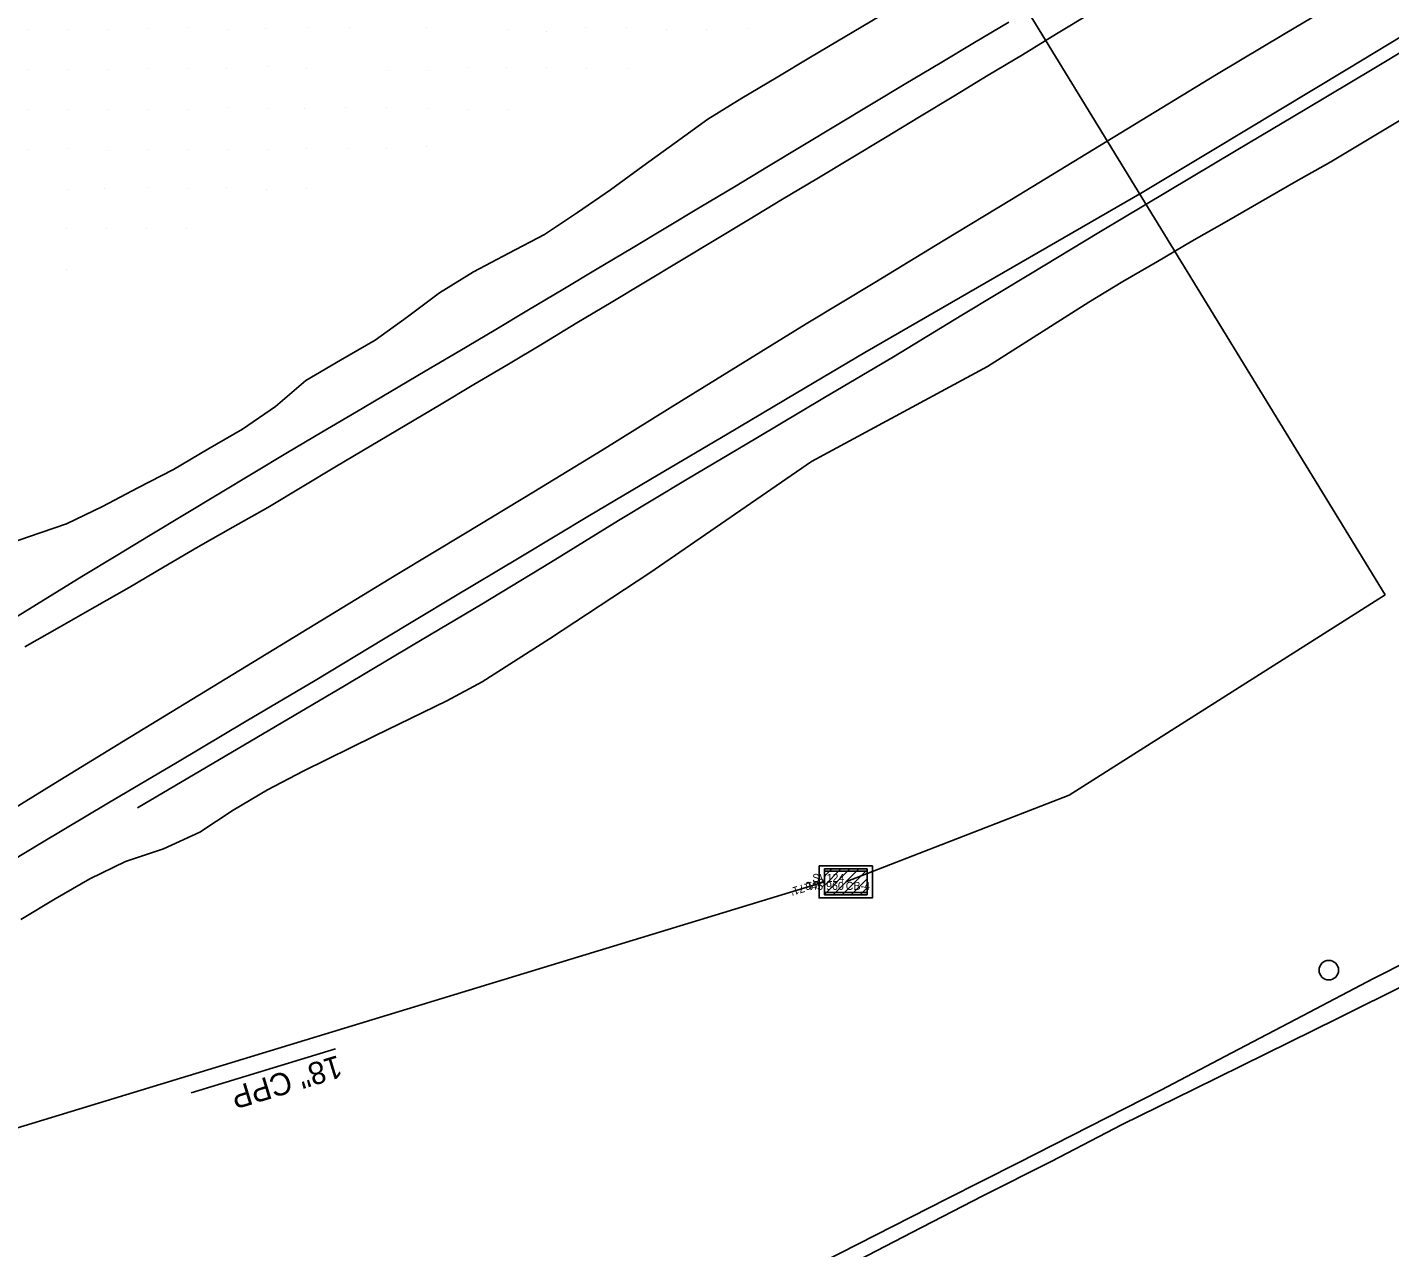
# Model space of a CAD drawing. Extents: x 2262025 to 2264532, y 740981 to 742724.
# Drawn here: x 2263228.5 to 2263398.7, y 741736.1 to 741888.7 of the extents above; entities that cross this region are included whole.
import ezdxf

# ---------------------------------------------------------------- set-up
doc = ezdxf.new("R2010")
doc.units = 0
for name, color, linetype in [('DR_X_Storm_Sewer', 7, 'Continuous'), ('DR_X_Text', 7, 'Continuous'), ('GE_X_Alignment_100_Bearings', 7, 'Continuous'), ('GE_X_Alignment_100_Cardinal_Points', 7, 'Continuous'), ('GE_X_Alignment_100_Curve_Data', 7, 'Continuous'), ('GE_X_Alignment_100_Stations', 7, 'Continuous'), ('Ground Shots', 7, 'Continuous'), ('HY_X_Spring_Cells', 7, 'Continuous'), ('RS_Raster1', 7, 'Continuous'), ('RW_X_CL', 7, 'Continuous'), ('RW_X_CL_1000_Distances', 7, 'Continuous'), ('RW_X_CL_100_Curve_Data', 7, 'Continuous'), ('RW_X_CL_100_Stations', 7, 'Continuous'), ('RW_X_CL_500_Curve_Data', 7, 'Continuous'), ('RW_X_CL_500_Stations', 7, 'Continuous'), ('SV_X_Control_Cells_Found', 7, 'Continuous'), ('SV_X_Text_Comment', 7, 'Continuous')]:
    doc.layers.add(name, color=color, linetype=linetype)

msp = doc.modelspace()

# ---------------------------------------------------------------- linework, layer by layer
at = {"layer": 'DR_X_Storm_Sewer'}
msp.add_line((2263328.09, 741781.86), (2263190.44, 741739.91), dxfattribs=at)
at = {"layer": 'DR_X_Text'}
msp.add_line((2263248.95, 741755.5), (2263267, 741761), dxfattribs=at)
at = {"layer": 'GE_X_Alignment_100_Bearings'}
msp.add_lwpolyline([(2263242.27, 741791.13), (2263250.88, 741796.21), (2263259.49, 741801.29), (2263268.11, 741806.37), (2263276.7, 741811.48), (2263285.3, 741816.59), (2263293.85, 741821.78), (2263302.36, 741827.03), (2263310.93, 741832.19), (2263319.52, 741837.3), (2263328.12, 741842.41), (2263336.72, 741847.51), (2263345.27, 741852.69), (2263353.83, 741857.86), (2263362.4, 741863.02), (2263370.98, 741868.16), (2263379.56, 741873.28), (2263388.15, 741878.41), (2263396.73, 741883.54), (2263405.31, 741888.68)], dxfattribs=at)
at = {"layer": 'GE_X_Alignment_100_Cardinal_Points'}
msp.add_lwpolyline([(2263325.57, 741733.16), (2263334.48, 741737.69), (2263343.4, 741742.23), (2263352.31, 741746.76), (2263361.22, 741751.3), (2263370.13, 741755.83), (2263378.99, 741760.47), (2263387.84, 741765.13), (2263396.69, 741769.79), (2263405.62, 741774.29), (2263414.58, 741778.74), (2263423.53, 741783.19), (2263432.48, 741787.64), (2263441.23, 741792.48), (2263450.22, 741796.85), (2263459.14, 741801.38), (2263463.94, 741803.49)], dxfattribs=at)
at = {"layer": 'GE_X_Alignment_100_Curve_Data'}
for points in [[(2263226.8, 741814.77), (2263231.05, 741817.4), (2263235.31, 741820.02), (2263239.58, 741822.62), (2263243.85, 741825.21), (2263248.13, 741827.8), (2263252.42, 741830.38), (2263256.7, 741832.96), (2263260.99, 741835.53), (2263265.3, 741838.07), (2263269.61, 741840.6), (2263273.91, 741843.15), (2263278.21, 741845.69), (2263282.52, 741848.24), (2263286.82, 741850.79), (2263291.11, 741853.35), (2263295.4, 741855.92), (2263299.69, 741858.48), (2263303.98, 741861.05), (2263308.27, 741863.61), (2263312.56, 741866.18), (2263316.85, 741868.75), (2263321.13, 741871.33), (2263325.41, 741873.91), (2263329.7, 741876.48), (2263333.98, 741879.06), (2263338.26, 741881.64), (2263342.55, 741884.21), (2263346.83, 741886.79), (2263351.13, 741889.34)], [(2263402.06, 741888.65), (2263393.5, 741883.49), (2263384.93, 741878.33), (2263376.36, 741873.17), (2263367.79, 741868.03), (2263359.13, 741863.03), (2263350.47, 741858.02), (2263341.81, 741853.02), (2263333.15, 741848.02), (2263324.55, 741842.93), (2263315.95, 741837.83), (2263307.33, 741832.76), (2263298.73, 741827.65), (2263290.16, 741822.5), (2263281.59, 741817.35), (2263273.02, 741812.19), (2263264.45, 741807.04), (2263255.85, 741801.93), (2263247.25, 741796.84), (2263238.64, 741791.74), (2263230.06, 741786.62), (2263221.49, 741781.45)]]:
    msp.add_lwpolyline(points, dxfattribs=at)
at = {"layer": 'GE_X_Alignment_100_Stations'}
msp.add_circle((2263391.12, 741770.82), 1.22, dxfattribs=at)
at = {"layer": 'Ground Shots'}
for p, q in [((2263228.5, 741888.46), (2263228.5, 741888.46)), ((2263233.51, 741888.46), (2263233.51, 741888.46)), ((2263238.56, 741888.46), (2263238.56, 741888.46)), ((2263243.46, 741888.5), (2263243.46, 741888.5)), ((2263248.46, 741888.64), (2263248.46, 741888.64)), ((2263253.45, 741888.45), (2263253.45, 741888.45)), ((2263258.31, 741888.49), (2263258.31, 741888.49)), ((2263263.45, 741888.64), (2263263.45, 741888.64)), ((2263268.73, 741888.67), (2263268.73, 741888.67)), ((2263278.36, 741888.64), (2263278.36, 741888.64)), ((2263288.6, 741888.38), (2263288.6, 741888.38)), ((2263293.4, 741888.13), (2263293.4, 741888.13)), ((2263298.18, 741888.64), (2263298.18, 741888.64)), ((2263303.42, 741888.61), (2263303.42, 741888.61)), ((2263308.42, 741888.43), (2263308.42, 741888.43)), ((2263313.34, 741888.43), (2263313.34, 741888.43)), ((2263318.49, 741888.48), (2263318.49, 741888.48)), ((2263258.66, 741883.82), (2263258.66, 741883.82)), ((2263228.58, 741883.4), (2263228.58, 741883.4)), ((2263233.56, 741883.42), (2263233.56, 741883.42)), ((2263238.64, 741883.41), (2263238.64, 741883.41)), ((2263243.59, 741883.58), (2263243.59, 741883.58)), ((2263248.61, 741883.5), (2263248.61, 741883.5)), ((2263253.35, 741883.52), (2263253.35, 741883.52)), ((2263263.33, 741883.54), (2263263.33, 741883.54)), ((2263273.62, 741883.3), (2263273.62, 741883.3)), ((2263278.48, 741883.22), (2263278.48, 741883.22)), ((2263283.64, 741883.64), (2263283.64, 741883.64)), ((2263288.4, 741883.61), (2263288.4, 741883.61)), ((2263293.31, 741883.66), (2263293.31, 741883.66)), ((2263298.4, 741883.51), (2263298.4, 741883.51)), ((2263303.44, 741883.53), (2263303.44, 741883.53)), ((2263253.47, 741878.66), (2263253.47, 741878.66)), ((2263268.26, 741878.69), (2263268.26, 741878.69)), ((2263273.41, 741878.66), (2263273.41, 741878.66)), ((2263278.56, 741878.58), (2263278.56, 741878.58)), ((2263228.57, 741878.4), (2263228.57, 741878.4)), ((2263233.52, 741878.4), (2263233.52, 741878.4)), ((2263238.63, 741878.46), (2263238.63, 741878.46)), ((2263243.55, 741878.42), (2263243.55, 741878.42)), ((2263248.49, 741878.38), (2263248.49, 741878.38)), ((2263258.5, 741878.47), (2263258.5, 741878.47)), ((2263263.19, 741878.56), (2263263.19, 741878.56)), ((2263283.51, 741878.42), (2263283.51, 741878.42)), ((2263288.46, 741878.38), (2263288.46, 741878.38)), ((2263233.51, 741873.59), (2263233.51, 741873.59)), ((2263263.44, 741873.57), (2263263.44, 741873.57)), ((2263268.58, 741873.55), (2263268.58, 741873.55)), ((2263273.43, 741873.48), (2263273.43, 741873.48)), ((2263278.39, 741873.83), (2263278.39, 741873.83)), ((2263228.49, 741873.45), (2263228.49, 741873.45)), ((2263238.5, 741873.32), (2263238.5, 741873.32)), ((2263243.52, 741873.38), (2263243.52, 741873.38)), ((2263248.45, 741873.4), (2263248.45, 741873.4)), ((2263253.51, 741873.46), (2263253.51, 741873.46)), ((2263258.58, 741873.41), (2263258.58, 741873.41)), ((2263233.46, 741868.43), (2263233.46, 741868.43)), ((2263238.17, 741868.56), (2263238.17, 741868.56)), ((2263243.48, 741868.6), (2263243.48, 741868.6)), ((2263248.46, 741868.47), (2263248.46, 741868.47)), ((2263253.44, 741868.61), (2263253.44, 741868.61)), ((2263258.43, 741868.38), (2263258.43, 741868.38)), ((2263263.44, 741868.56), (2263263.44, 741868.56)), ((2263233.35, 741863.56), (2263233.35, 741863.56)), ((2263238.38, 741863.57), (2263238.38, 741863.57)), ((2263243.42, 741863.55), (2263243.42, 741863.55)), ((2263248.38, 741863.48), (2263248.38, 741863.48)), ((2263233.45, 741858.39), (2263233.45, 741858.39))]:
    msp.add_line(p, q, dxfattribs=at)
at = {"layer": 'RW_X_CL_1000_Distances'}
for points in [[(2263223.49, 741788.99), (2263232, 741794.24), (2263240.53, 741799.45), (2263249.06, 741804.67), (2263257.6, 741809.88), (2263266.13, 741815.09), (2263274.68, 741820.27), (2263283.24, 741825.45), (2263291.79, 741830.63), (2263300.33, 741835.84), (2263308.83, 741841.1), (2263317.32, 741846.36), (2263325.83, 741851.62), (2263334.38, 741856.8), (2263342.93, 741861.98), (2263351.48, 741867.16), (2263360.01, 741872.37), (2263368.55, 741877.57), (2263377.08, 741882.78), (2263385.65, 741887.92), (2263394.24, 741893.05), (2263402.82, 741898.18)], [(2263361.39, 741890.43), (2263357.11, 741887.85), (2263352.83, 741885.26), (2263348.55, 741882.68), (2263344.27, 741880.09), (2263339.99, 741877.51), (2263335.71, 741874.92), (2263331.43, 741872.34), (2263327.15, 741869.76), (2263322.87, 741867.18), (2263318.59, 741864.61), (2263314.31, 741862.03), (2263310.02, 741859.45), (2263305.74, 741856.88), (2263301.45, 741854.3), (2263297.17, 741851.72), (2263292.89, 741849.13), (2263288.6, 741846.57), (2263284.3, 741844.02), (2263280.01, 741841.46), (2263275.71, 741838.91), (2263271.41, 741836.36), (2263267.11, 741833.81), (2263262.82, 741831.24), (2263258.53, 741828.66), (2263254.19, 741826.19), (2263249.84, 741823.72), (2263245.53, 741821.19), (2263241.21, 741818.66), (2263236.87, 741816.18), (2263232.53, 741813.7), (2263228.19, 741811.22)]]:
    msp.add_lwpolyline(points, dxfattribs=at)
at = {"layer": 'RW_X_CL_100_Curve_Data'}
for p, q in [((2263328.09, 741780.29), (2263331.28, 741783.48)), ((2263328.09, 741781.42), (2263330.14, 741783.48)), ((2263328.09, 741782.56), (2263329.01, 741783.48)), ((2263328.09, 741780.29), (2263331.28, 741783.48)), ((2263328.09, 741781.42), (2263330.14, 741783.48)), ((2263328.09, 741782.56), (2263329.01, 741783.48)), ((2263329.18, 741780.25), (2263332.41, 741783.48)), ((2263329.18, 741780.25), (2263332.41, 741783.48)), ((2263330.31, 741780.25), (2263333.43, 741783.36)), ((2263330.31, 741780.25), (2263333.43, 741783.36)), ((2263331.44, 741780.25), (2263333.43, 741782.23)), ((2263331.44, 741780.25), (2263333.43, 741782.23)), ((2263332.57, 741780.25), (2263333.43, 741781.1)), ((2263332.57, 741780.25), (2263333.43, 741781.1))]:
    msp.add_line(p, q, dxfattribs=at)
for points in [[(2263327.43, 741783.86), (2263334.09, 741783.86), (2263334.09, 741779.86), (2263327.43, 741779.86)], [(2263327.43, 741783.86), (2263334.09, 741783.86), (2263334.09, 741779.86), (2263327.43, 741779.86)], [(2263328.09, 741783.48), (2263333.43, 741783.48), (2263333.43, 741780.25), (2263328.09, 741780.25)], [(2263328.09, 741783.48), (2263333.43, 741783.48), (2263333.43, 741780.25), (2263328.09, 741780.25)], [(2263328.09, 741783.2), (2263333.43, 741783.2), (2263333.43, 741780.53), (2263328.09, 741780.53)], [(2263328.09, 741783.2), (2263333.43, 741783.2), (2263333.43, 741780.53), (2263328.09, 741780.53)]]:
    msp.add_lwpolyline(points, close=True, dxfattribs=at)
at = {"layer": 'RW_X_CL_100_Stations'}
for p, q in [((2263330.76, 741783.86), (2263330.76, 741783.86)), ((2263330.76, 741783.86), (2263330.76, 741783.86)), ((2263328.09, 741781.86), (2263328.09, 741781.86)), ((2263328.09, 741781.86), (2263328.09, 741781.86)), ((2263330.76, 741783.2), (2263330.76, 741783.2)), ((2263330.76, 741783.2), (2263330.76, 741783.2)), ((2263330.76, 741781.86), (2263330.76, 741781.86)), ((2263330.76, 741781.86), (2263330.76, 741781.86)), ((2263330.76, 741781.86), (2263330.76, 741781.86)), ((2263330.76, 741781.86), (2263330.76, 741781.86)), ((2263333.43, 741781.86), (2263333.43, 741781.86)), ((2263333.43, 741781.86), (2263333.43, 741781.86)), ((2263330.76, 741780.53), (2263330.76, 741780.53)), ((2263330.76, 741780.53), (2263330.76, 741780.53)), ((2263330.76, 741780.25), (2263330.76, 741780.25)), ((2263330.76, 741780.25), (2263330.76, 741780.25)), ((2263330.76, 741779.86), (2263330.76, 741779.86)), ((2263330.76, 741779.86), (2263330.76, 741779.86))]:
    msp.add_line(p, q, dxfattribs=at)
at = {"layer": 'RW_X_CL_500_Curve_Data'}
msp.add_lwpolyline([(2263330.2, 741733.44), (2263339.02, 741738.04), (2263347.88, 741742.61), (2263356.45, 741746.9), (2263365.31, 741751.52), (2263374.29, 741755.93), (2263383.25, 741760.36), (2263392.21, 741764.8), (2263401.18, 741769.23), (2263409.98, 741773.97), (2263418.79, 741778.71), (2263427.63, 741783.39), (2263436.43, 741788.14), (2263445.22, 741792.9), (2263454, 741797.68), (2263462.79, 741801.94), (2263467.51, 741799.66)], dxfattribs=at)
at = {"layer": 'RW_X_CL_500_Stations'}
msp.add_line((2263303.48, 741972.55), (2263398.17, 741817.73), dxfattribs=at)
msp.add_lwpolyline([(2263398.17, 741817.73), (2263358.68, 741792.7), (2263330.76, 741781.86)], dxfattribs=at)
at = {"layer": 'SV_X_Control_Cells_Found'}
for points in [[(2263334.93, 741890.04), (2263330.64, 741887.5), (2263326.34, 741884.95), (2263322.05, 741882.38), (2263317.76, 741879.81), (2263313.51, 741877.19), (2263309.46, 741874.25), (2263305.41, 741871.32), (2263301.37, 741868.38), (2263297.25, 741865.55), (2263293.1, 741862.77), (2263288.68, 741860.43), (2263284.25, 741858.11), (2263280, 741855.48), (2263275.98, 741852.5), (2263271.94, 741849.57), (2263267.61, 741847.06), (2263263.3, 741844.53), (2263259.5, 741841.28), (2263255.39, 741838.45), (2263251.07, 741835.93), (2263246.74, 741833.42), (2263242.32, 741831.1), (2263237.88, 741828.8), (2263233.39, 741826.6), (2263228.66, 741824.98), (2263223.93, 741823.36)], [(2263227.68, 741777.14), (2263231.96, 741779.73), (2263236.29, 741782.23), (2263240.78, 741784.4), (2263245.52, 741785.99), (2263250.05, 741788.07), (2263254.23, 741790.82), (2263258.52, 741793.38), (2263262.97, 741795.68), (2263271.93, 741800.11), (2263280.91, 741804.49), (2263285.31, 741806.87), (2263293.74, 741812.23), (2263306.27, 741820.48), (2263326.5, 741834.41), (2263348.47, 741846.3), (2263361.12, 741854.31), (2263365.4, 741856.89), (2263369.7, 741859.42), (2263374.02, 741861.93), (2263378.35, 741864.42), (2263387.02, 741869.39), (2263391.36, 741871.88), (2263399.93, 741876.97)]]:
    msp.add_lwpolyline(points, dxfattribs=at)

# ---------------------------------------------------------------- texts
at = {"layer": 'DR_X_Text'}
msp.add_text('18" CPP', height=2.8, rotation=196.9486, dxfattribs=at).set_placement((2263267.3, 741760.23))
at = {"layer": 'HY_X_Spring_Cells'}
msp.add_text('945.960', height=1, dxfattribs=at).set_placement((2263325.7, 741780.86))
msp.add_text('945.960', height=1, dxfattribs=at).set_placement((2263325.7, 741780.86))
at = {"layer": 'RS_Raster1'}
msp.add_text("941.71'", height=1, rotation=196.9486, dxfattribs=at).set_placement((2263327.95, 741782.34))
at = {"layer": 'RW_X_CL'}
msp.add_text('CB-4', height=1, dxfattribs=at).set_placement((2263330.76, 741780.86))
msp.add_text('CB-4', height=1, dxfattribs=at).set_placement((2263330.76, 741780.86))
at = {"layer": 'SV_X_Text_Comment'}
msp.add_text('SV124', height=1, dxfattribs=at).set_placement((2263326.58, 741781.86))
msp.add_text('SV124', height=1, dxfattribs=at).set_placement((2263326.58, 741781.86))

doc.saveas('drawing.dxf')
